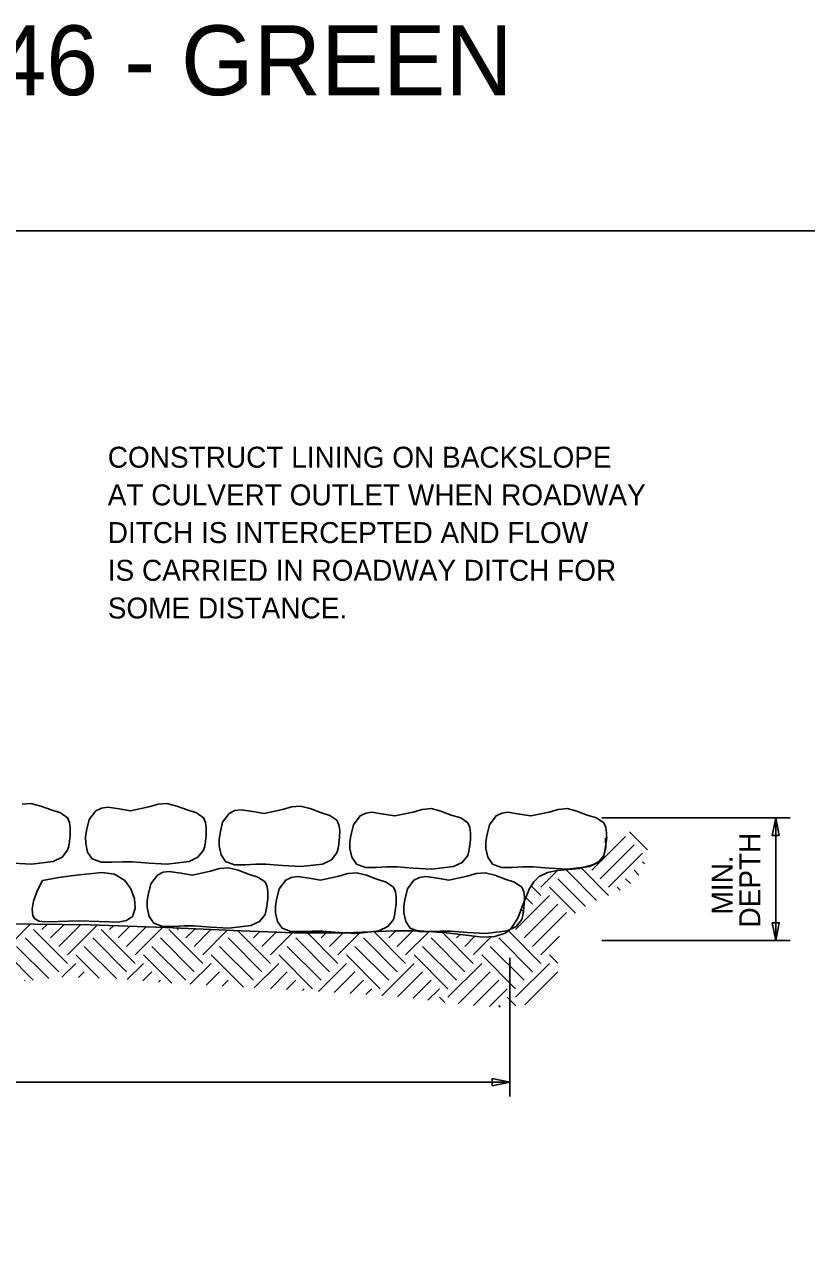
# Model space of a CAD drawing. Extents: x -439.1 to -407.9, y -458.1 to -436.2.
# Drawn here: x -424 to -418.4, y -444.91 to -436.2 of the extents above; entities that cross this region are included whole.
import ezdxf

# ---------------------------------------------------------------- set-up
doc = ezdxf.new("R2010")
doc.units = 0
for name, color, linetype in [('Draft_Named_Boundary', 7, 'Continuous'), ('Level 4', 7, 'Continuous'), ('Level 46', 7, 'Continuous')]:
    doc.layers.add(name, color=color, linetype=linetype)

msp = doc.modelspace()

# ---------------------------------------------------------------- linework, layer by layer
at = {"layer": 'Draft_Named_Boundary'}
msp.add_lwpolyline([(-439.109, -458.0508), (-407.859, -458.0508), (-407.859, -437.6758), (-439.109, -437.6758)], close=True, dxfattribs=at)
at = {"layer": 'Level 4'}
for p, q in [((-419.8623, -441.881), (-418.5146, -441.881)), ((-418.6174, -441.881), (-418.6174, -442.7589)), ((-419.9358, -442.2561), (-419.6934, -442.0136)), ((-419.8364, -442.0354), (-419.8226, -442.0216)), ((-419.5358, -442.1106), (-419.6659, -441.9805)), ((-419.8752, -442.3167), (-419.6328, -442.0742)), ((-419.8146, -442.3773), (-419.5722, -442.1348)), ((-419.5574, -442.2102), (-419.5722, -442.1955)), ((-420.2995, -442.3773), (-420.1803, -442.258)), ((-419.9006, -442.4732), (-420.1177, -442.2561)), ((-419.8146, -442.4379), (-420.0126, -442.2399)), ((-419.5972, -442.2917), (-419.6328, -442.2561)), ((-420.2995, -442.4379), (-420.3673, -442.3702)), ((-420.0518, -442.5644), (-420.2389, -442.3773)), ((-419.9803, -442.5147), (-420.1783, -442.3167)), ((-419.7314, -442.3999), (-419.754, -442.3773)), ((-419.6589, -442.3511), (-419.6934, -442.3167)), ((-420.4814, -442.6804), (-420.2389, -442.4379)), ((-420.3601, -442.4985), (-420.4072, -442.4515)), ((-420.4208, -442.5591), (-420.442, -442.5379)), ((-420.4208, -442.741), (-420.1783, -442.4985)), ((-420.3601, -442.8016), (-420.1177, -442.5591)), ((-424.1788, -442.8622), (-423.9573, -442.6407)), ((-423.8758, -442.6804), (-423.8373, -442.6419)), ((-423.8151, -442.741), (-423.7176, -442.6435)), ((-423.7545, -442.8016), (-423.5986, -442.6457)), ((-423.6939, -442.8622), (-423.4807, -442.649)), ((-423.3908, -442.6804), (-423.3641, -442.6537)), ((-423.7545, -442.9834), (-423.997, -442.741)), ((-423.6939, -442.9228), (-423.9364, -442.6804)), ((-423.2696, -442.9834), (-423.5121, -442.741)), ((-423.209, -442.9228), (-423.4515, -442.6804)), ((-423.3302, -442.741), (-423.2476, -442.6583)), ((-423.2696, -442.8016), (-423.131, -442.663)), ((-423.209, -442.8622), (-423.0144, -442.6676)), ((-422.7847, -442.9834), (-423.0272, -442.741)), ((-422.7241, -442.9228), (-422.9665, -442.6804)), ((-422.9059, -442.6804), (-422.8979, -442.6723)), ((-422.8453, -442.741), (-422.7813, -442.677)), ((-422.7847, -442.8016), (-422.6647, -442.6816)), ((-422.7241, -442.8622), (-422.5482, -442.6863)), ((-422.2998, -442.9834), (-422.5422, -442.741)), ((-422.2392, -442.9228), (-422.4727, -442.6893)), ((-422.3604, -442.741), (-422.3123, -442.6929)), ((-422.2998, -442.8016), (-422.1934, -442.6952)), ((-422.2392, -442.8622), (-422.0744, -442.6975)), ((-421.8149, -442.9834), (-422.0573, -442.741)), ((-421.7543, -442.9228), (-421.9778, -442.6993)), ((-421.8755, -442.741), (-421.8366, -442.702)), ((-421.8149, -442.8016), (-421.7176, -442.7043)), ((-421.7543, -442.8622), (-421.5919, -442.6999)), ((-421.33, -442.9834), (-421.5724, -442.741)), ((-421.2694, -442.9228), (-421.4966, -442.6955)), ((-421.3906, -442.741), (-421.339, -442.6894)), ((-421.33, -442.8016), (-421.2227, -442.6943)), ((-421.2694, -442.8622), (-421.1064, -442.6992)), ((-420.8451, -442.9834), (-421.0875, -442.741)), ((-420.7844, -442.9228), (-421.0037, -442.7036)), ((-420.9057, -442.741), (-420.8822, -442.7176)), ((-420.8451, -442.8016), (-420.7725, -442.7291)), ((-420.7844, -442.8622), (-420.6534, -442.7312)), ((-420.3601, -442.9834), (-420.6026, -442.741)), ((-420.2995, -442.9228), (-420.5367, -442.6856)), ((-420.2995, -442.8622), (-420.1665, -442.7292)), ((-423.8278, -443.0314), (-424.0576, -442.8016)), ((-423.3421, -443.0322), (-423.5727, -442.8016)), ((-422.8453, -443.044), (-423.0878, -442.8016)), ((-422.3604, -443.044), (-422.6029, -442.8016)), ((-421.8755, -443.044), (-422.118, -442.8016)), ((-421.3906, -443.044), (-421.633, -442.8016)), ((-420.9057, -443.044), (-421.1481, -442.8016)), ((-420.4208, -443.044), (-420.6632, -442.8016)), ((-419.8623, -442.7589), (-418.5146, -442.7589)), ((-423.9382, -443.0422), (-424.1182, -442.8622)), ((-423.4666, -443.0289), (-423.6333, -442.8622)), ((-422.9447, -443.0659), (-423.1484, -442.8622)), ((-422.4317, -443.094), (-422.6635, -442.8622)), ((-421.9361, -443.1047), (-422.1786, -442.8622)), ((-421.4512, -443.1047), (-421.6937, -442.8622)), ((-420.9663, -443.1047), (-421.2087, -442.8622)), ((-420.4814, -443.1047), (-420.7238, -442.8622)), ((-420.5223, -442.8845), (-420.5223, -443.8773)), ((-420.1793, -442.9218), (-420.2389, -442.8622)), ((-423.7326, -443.0221), (-423.6333, -442.9228)), ((-423.6144, -443.0251), (-423.5727, -442.9834)), ((-423.2644, -443.0388), (-423.1484, -442.9228)), ((-423.1527, -443.0483), (-423.0878, -442.9834)), ((-422.8137, -443.073), (-422.6635, -442.9228)), ((-422.6988, -443.0793), (-422.6029, -442.9834)), ((-422.354, -443.0982), (-422.1786, -442.9228)), ((-422.239, -443.1045), (-422.118, -442.9834)), ((-421.8943, -443.1235), (-421.6937, -442.9228)), ((-421.7808, -443.1312), (-421.633, -442.9834)), ((-421.4404, -443.1544), (-421.2087, -442.9228)), ((-421.3269, -443.1622), (-421.1481, -442.9834)), ((-420.9663, -443.1653), (-420.7238, -442.9228)), ((-420.8937, -443.2139), (-420.6632, -442.9834)), ((-420.4814, -443.1653), (-420.2389, -442.9228)), ((-420.4152, -443.2203), (-420.1794, -442.9846)), ((-424.0013, -443.0484), (-423.997, -443.044)), ((-423.041, -443.0579), (-423.0272, -443.044)), ((-422.5838, -443.0856), (-422.5422, -443.044)), ((-422.1241, -443.1108), (-422.0573, -443.044)), ((-421.6673, -443.139), (-421.5724, -443.044)), ((-421.2164, -443.1729), (-421.0875, -443.044)), ((-420.784, -443.2255), (-420.6026, -443.044)), ((-422.0092, -443.1171), (-421.9967, -443.1047)), ((-421.5539, -443.1467), (-421.5118, -443.1047)), ((-421.1094, -443.1872), (-421.0269, -443.1047)), ((-420.9897, -443.2024), (-421.0269, -443.1653)), ((-420.669, -443.2317), (-420.542, -443.1047)), ((-420.4808, -443.2265), (-420.542, -443.1653)), ((-420.5926, -443.2358), (-420.6026, -443.2259)), ((-431.8697, -443.7744), (-420.5223, -443.7744))]:
    msp.add_line(p, q, dxfattribs=at)
for points in [[(-424.0186, -441.7837), (-423.9553, -441.7779), (-423.8848, -441.7959), (-423.8108, -441.8239), (-423.7436, -441.8447), (-423.6925, -441.8797), (-423.6781, -441.9133), (-423.6728, -441.952), (-423.6738, -442.0016), (-423.6793, -442.0506), (-423.6841, -442.0828), (-423.6925, -442.113), (-423.7324, -442.1629), (-423.7959, -442.193), (-423.9521, -442.2116), (-424.082, -442.2044)], [(-419.8368, -442.0266), (-419.8337, -442.094), (-419.8513, -442.1565), (-419.8809, -442.1912), (-419.9222, -442.2159), (-420.0244, -442.243), (-420.1832, -442.2583), (-420.2536, -442.2719), (-420.313, -442.3007), (-420.3503, -442.3385), (-420.3806, -442.3873), (-420.4284, -442.5027), (-420.4657, -442.599), (-420.5149, -442.6759), (-420.555, -442.7059), (-420.6294, -442.7301), (-420.7167, -442.735), (-420.9766, -442.7047), (-421.1704, -442.6892), (-421.3513, -442.6889), (-421.698, -442.7047), (-422.069, -442.705), (-422.4482, -442.6903), (-422.9911, -442.6655), (-423.5303, -442.647), (-424.1356, -442.6392)]]:
    msp.add_lwpolyline(points, dxfattribs=at)
for points in [[(-423.5558, -441.9717), (-423.5374, -441.8931), (-423.49, -441.8304), (-423.4497, -441.8109), (-423.4046, -441.8041), (-423.3218, -441.8165), (-423.2403, -441.8304), (-423.109, -441.8025), (-423.044, -441.7837), (-422.9807, -441.7779), (-422.9101, -441.7959), (-422.8362, -441.8239), (-422.769, -441.8447), (-422.7179, -441.8797), (-422.7035, -441.9133), (-422.6982, -441.952), (-422.6992, -442.0016), (-422.7047, -442.0506), (-422.7095, -442.0828), (-422.7179, -442.113), (-422.7578, -442.1629), (-422.8213, -442.193), (-422.9775, -442.2116), (-423.1074, -442.2044), (-423.2272, -442.1952), (-423.2989, -442.1953), (-423.375, -442.1984), (-423.4521, -442.1984), (-423.5163, -442.1754), (-423.5486, -442.1265), (-423.5623, -442.0637), (-423.5631, -442.0168), (-423.5558, -441.9717)], [(-422.5995, -441.9901), (-422.5812, -441.9115), (-422.5338, -441.8488), (-422.4934, -441.8293), (-422.4484, -441.8225), (-422.3656, -441.8349), (-422.2841, -441.8488), (-422.1528, -441.8209), (-422.0878, -441.8021), (-422.0245, -441.7962), (-421.9539, -441.8143), (-421.8799, -441.8423), (-421.8128, -441.8631), (-421.7616, -441.8981), (-421.7473, -441.9317), (-421.7419, -441.9704), (-421.7429, -442.02), (-421.7485, -442.069), (-421.7533, -442.1012), (-421.7616, -442.1314), (-421.8016, -442.1813), (-421.865, -442.2114), (-422.0212, -442.23), (-422.1512, -442.2228), (-422.271, -442.2135), (-422.3427, -442.2136), (-422.4188, -442.2168), (-422.4959, -442.2168), (-422.5601, -442.1938), (-422.5923, -442.1449), (-422.6061, -442.0821), (-422.6069, -442.0352), (-422.5995, -441.9901)], [(-421.6617, -442.0085), (-421.6433, -441.9299), (-421.596, -441.8672), (-421.5556, -441.8477), (-421.5106, -441.8409), (-421.4278, -441.8533), (-421.3463, -441.8672), (-421.215, -441.8393), (-421.15, -441.8205), (-421.0867, -441.8146), (-421.0161, -441.8327), (-420.9421, -441.8606), (-420.875, -441.8815), (-420.8238, -441.9165), (-420.8094, -441.9501), (-420.8041, -441.9888), (-420.8051, -442.0384), (-420.8107, -442.0874), (-420.8154, -442.1196), (-420.8238, -442.1498), (-420.8637, -442.1997), (-420.9272, -442.2297), (-421.0834, -442.2484), (-421.2134, -442.2411), (-421.3331, -442.2319), (-421.4048, -442.232), (-421.481, -442.2352), (-421.5581, -442.2352), (-421.6223, -442.2122), (-421.6545, -442.1633), (-421.6683, -442.1005), (-421.6691, -442.0536), (-421.6617, -442.0085)], [(-420.6871, -442.0085), (-420.6687, -441.9299), (-420.6214, -441.8672), (-420.581, -441.8477), (-420.536, -441.8409), (-420.4532, -441.8533), (-420.3717, -441.8672), (-420.2404, -441.8393), (-420.1754, -441.8205), (-420.1121, -441.8146), (-420.0415, -441.8327), (-419.9675, -441.8606), (-419.9004, -441.8815), (-419.8492, -441.9165), (-419.8348, -441.9501), (-419.8295, -441.9888), (-419.8305, -442.0384), (-419.8361, -442.0874), (-419.8408, -442.1196), (-419.8492, -442.1498), (-419.8891, -442.1997), (-419.9526, -442.2297), (-420.1088, -442.2484), (-420.2388, -442.2411), (-420.3585, -442.2319), (-420.4302, -442.232), (-420.5064, -442.2352), (-420.5835, -442.2352), (-420.6477, -442.2122), (-420.6799, -442.1633), (-420.6937, -442.1005), (-420.6945, -442.0536), (-420.6871, -442.0085)], [(-418.5912, -442.0074), (-418.6174, -441.881), (-418.6437, -442.0074)], [(-423.8711, -442.3289), (-423.754, -442.3074), (-423.632, -442.2922), (-423.4438, -442.2711), (-423.3565, -442.2837), (-423.2826, -442.3289), (-423.2402, -442.3887), (-423.2138, -442.4606), (-423.2079, -442.5309), (-423.2275, -442.5864), (-423.2698, -442.6154), (-423.3293, -442.6269), (-423.4665, -442.6232), (-423.6131, -442.6179), (-423.7607, -442.6232), (-423.8546, -442.6262), (-423.8956, -442.6203), (-423.9262, -442.6048), (-423.9414, -442.5823), (-423.9473, -442.5355), (-423.9374, -442.4786), (-423.9081, -442.3989), (-423.8711, -442.3289)], [(-423.1144, -442.4314), (-423.0961, -442.3528), (-423.0487, -442.2902), (-423.0083, -442.2706), (-422.9633, -442.2639), (-422.8805, -442.2762), (-422.799, -442.2902), (-422.6677, -442.2622), (-422.6027, -442.2434), (-422.5394, -442.2376), (-422.4688, -442.2556), (-422.3948, -442.2836), (-422.3277, -442.3045), (-422.2765, -442.3394), (-422.2621, -442.3731), (-422.2568, -442.4117), (-422.2578, -442.4613), (-422.2634, -442.5103), (-422.2682, -442.5425), (-422.2765, -442.5727), (-422.3165, -442.6226), (-422.3799, -442.6527), (-422.5361, -442.6713), (-422.6661, -442.6641), (-422.7858, -442.6549), (-422.8576, -442.655), (-422.9337, -442.6582), (-423.0108, -442.6582), (-423.075, -442.6352), (-423.1072, -442.5862), (-423.121, -442.5235), (-423.1218, -442.4765), (-423.1144, -442.4314)], [(-422.195, -442.4682), (-422.1766, -442.3896), (-422.1293, -442.3269), (-422.0889, -442.3074), (-422.0438, -442.3006), (-421.961, -442.313), (-421.8795, -442.3269), (-421.7482, -442.299), (-421.6833, -442.2802), (-421.62, -442.2744), (-421.5494, -442.2924), (-421.4754, -442.3204), (-421.4083, -442.3412), (-421.3571, -442.3762), (-421.3427, -442.4098), (-421.3374, -442.4485), (-421.3384, -442.4981), (-421.3439, -442.5471), (-421.3487, -442.5793), (-421.3571, -442.6095), (-421.397, -442.6594), (-421.4605, -442.6895), (-421.6167, -442.7081), (-421.7466, -442.7009), (-421.8664, -442.6917), (-421.9381, -442.6917), (-422.0143, -442.6949), (-422.0914, -442.6949), (-422.1556, -442.6719), (-422.1878, -442.623), (-422.2016, -442.5602), (-422.2024, -442.5133), (-422.195, -442.4682)], [(-421.2755, -442.4682), (-421.2572, -442.3896), (-421.2098, -442.3269), (-421.1694, -442.3074), (-421.1244, -442.3006), (-421.0416, -442.313), (-420.9601, -442.3269), (-420.8288, -442.299), (-420.7638, -442.2802), (-420.7005, -442.2744), (-420.6299, -442.2924), (-420.5559, -442.3204), (-420.4888, -442.3412), (-420.4376, -442.3762), (-420.4233, -442.4098), (-420.4179, -442.4485), (-420.4189, -442.4981), (-420.4245, -442.5471), (-420.4293, -442.5793), (-420.4376, -442.6095), (-420.4776, -442.6594), (-420.541, -442.6895), (-420.6972, -442.7081), (-420.8272, -442.7009), (-420.947, -442.6917), (-421.0187, -442.6917), (-421.0948, -442.6949), (-421.1719, -442.6949), (-421.2361, -442.6719), (-421.2683, -442.623), (-421.2821, -442.5602), (-421.2829, -442.5133), (-421.2755, -442.4682)], [(-418.6437, -442.6324), (-418.6174, -442.7589), (-418.5912, -442.6324)], [(-420.6487, -443.8007), (-420.5223, -443.7744), (-420.6487, -443.7482)]]:
    msp.add_lwpolyline(points, close=True, dxfattribs=at)

# ---------------------------------------------------------------- texts
for s, p in [('CONSTRUCT LINING ON BACKSLOPE ', (-423.4045, -439.3727)), ('AT CULVERT OUTLET WHEN ROADWAY ', (-423.4045, -439.6427)), ('DITCH IS INTERCEPTED AND FLOW ', (-423.4045, -439.9127)), ('IS CARRIED IN ROADWAY DITCH FOR ', (-423.4045, -440.1827)), ('SOME DISTANCE.', (-423.4045, -440.4527))]:
    msp.add_text(s, height=0.15, dxfattribs=at).set_placement(p)
for s, p in [('DEPTH', (-418.7284, -442.6668)), ('MIN.', (-418.9261, -442.5729))]:
    msp.add_text(s, height=0.15, rotation=90, dxfattribs=at).set_placement(p)
at = {"layer": 'Level 46'}
msp.add_text('METRIC - LEVEL 46 - GREEN', height=0.5, dxfattribs=at).set_placement((-429.6416, -436.7047))

doc.saveas('drawing.dxf')
